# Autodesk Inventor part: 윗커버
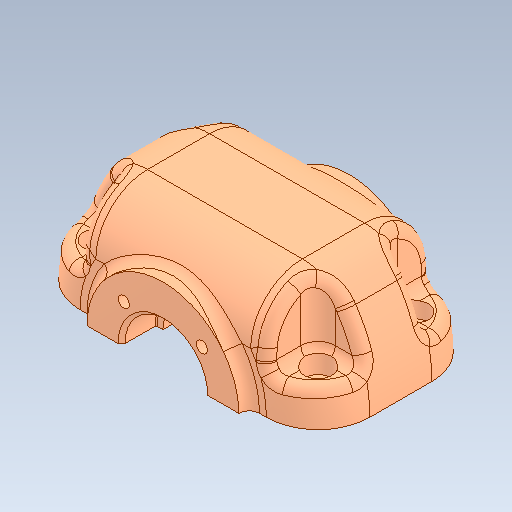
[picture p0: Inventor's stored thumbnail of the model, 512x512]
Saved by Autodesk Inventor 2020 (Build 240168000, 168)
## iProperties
Created: 2024-07
Part Number: 윗커버
Material: 일반
Document SubType Name: Modeling
Designer: oem
Density: 1 g/cm^3
Appearance: 기본값
Author: jhkim
Sending System: Autodesk Inventor 2025
Preprocessor: ST-DEVELOPER v20
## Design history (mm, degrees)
feature "솔리드1"
node "솔리드2"
